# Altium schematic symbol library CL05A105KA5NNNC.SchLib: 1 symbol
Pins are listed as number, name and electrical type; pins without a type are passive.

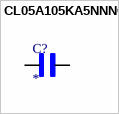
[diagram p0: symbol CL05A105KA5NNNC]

## CL05A105KA5NNNC
designator C?
Multilayer Ceramic Capacitors MLCC - SMD/SMT 1uF+/-10% 25V X5R 1005; MF: Samsung Electro-Mechanics; MP: CL05A105KA5NNNC
footprint CAPC1005X55N
pins: 1, 2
